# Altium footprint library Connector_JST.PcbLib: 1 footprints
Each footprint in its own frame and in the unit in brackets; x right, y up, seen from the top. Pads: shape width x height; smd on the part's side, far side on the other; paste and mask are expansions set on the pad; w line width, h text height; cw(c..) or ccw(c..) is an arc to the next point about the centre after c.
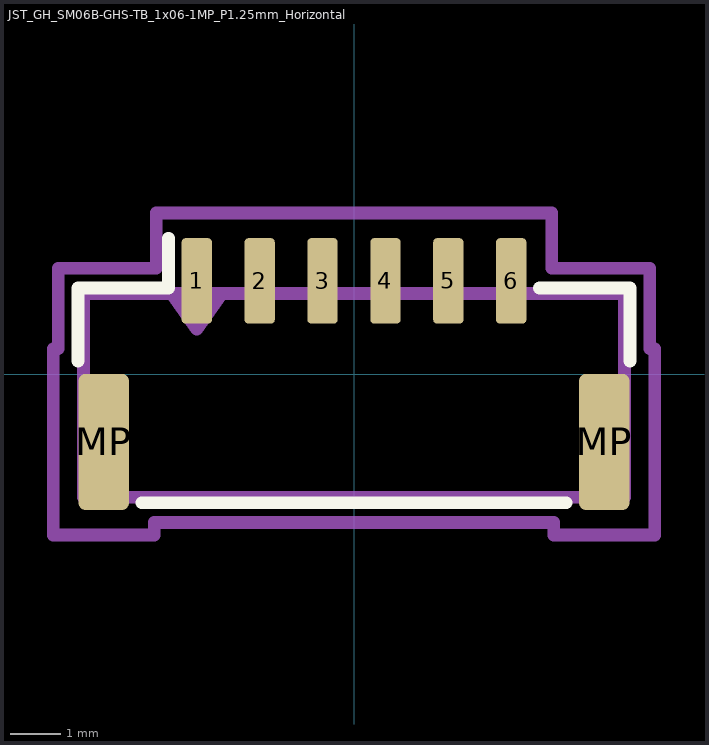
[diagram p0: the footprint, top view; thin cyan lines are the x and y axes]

## JST_GH_SM06B-GHS-TB_1x06-1MP_P1.25mm_Horizontal [mm]
pads (8):
  rrect25% 0.6x1.7 smd: 1(-3.125,1.85) 2(-1.875,1.85) 3(-0.625,1.85) 4(0.625,1.85) 5(1.875,1.85) 6(3.125,1.85)
  rrect25% 1x2.7 smd: MP(-4.975,-1.35) MP(4.975,-1.35)
F.SilkS:
  lines w0.254: -5.485,0.26 -5.485,1.71 -3.685,1.71 -3.685,2.7 ; -4.215,-2.56 4.215,-2.56 ; 3.685,1.71 5.485,1.71 5.485,0.26
F.CrtYd:
  lines w0.254: -5.98,-3.2 -5.98,0.5 -5.88,0.5 -5.88,2.1 -3.93,2.1 -3.93,3.2 3.93,3.2 3.93,2.1 5.88,2.1 5.88,0.5 5.98,0.5 5.98,-3.2 3.97,-3.2 3.97,-2.95 -3.97,-2.95 -3.97,-3.2 -5.98,-3.2
F.Fab:
  lines w0.254: -3.625,1.6 -3.125,0.893 -2.625,1.6 ; -5.375,-2.45 -5.375,1.6 5.375,1.6 5.375,-2.45 -5.375,-2.45
  text "'.Designator'" at -4.047,-0.84 h1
